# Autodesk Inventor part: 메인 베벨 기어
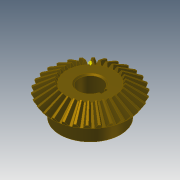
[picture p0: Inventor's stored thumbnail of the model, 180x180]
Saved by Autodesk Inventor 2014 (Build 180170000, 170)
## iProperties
Created: 2014-10
Part Number: 메인 베벨 기어
Material: Steel, Mild
Document SubType Name: Modeling
Designer: KYOUNG IL JANG
Categories: <?xml version="1.0" encoding="UTF-16"?> <MemberInstance><Categories><FamilyTemplate><FamilyTemplateParameter ValueType="xs:double" Id="1" ObjectReferenceKey="da
Mass: 269.583 g
Surface Area: 108.837 cm^2
Volume: 34.2981 cm^3
Density: 7.86 g/cm^3
Appearance: Brindle
CustomPartVersion: 1
Company: 한국ATC센터
Author: KYOUNG IL JANG
Revision Number: 1
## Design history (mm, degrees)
node "맨 위 점"
node "메쉬 평면2"
sketch "톱니 본체 스케치"
  geometry: L1 (0, 0)-(28.669, -21.997); L2 (28.669, -21.997)-(31.109, -18.336); L3 (31.109, -18.336)-(0, 0); L4 (30, -20)-(0, 0); L5 (17.219, -13.212)-(18.685, -11.013); L6 (28.669, -21.997)-(17.219, -13.212); L7 (31.109, -18.336)-(18.685, -11.013); L8 (0, -39.387)-(0, 6.564) reference; L9 (0, -20)-(31.109, -20)
  constraints: 16 end point, 4 point on line, 3 perpendicular, 2 collinear, 1 horizontal alignment, 1 vertical alignment
  dimensions: "d0" = 60 diameter of L4.start L8 (= da_de); "d1" = 57.33744 diameter of L1.end L8 (= da_dfe); "d2" = 62.2188 diameter of L2.end L8 (= da_dae); "d3" = 14.4 distance between parallel lines of L2 L5 (= da_b); "d4" = 18.3359 vertical distance of L2.end L1.start (= da_ve)
revolve "톱니 본체" sketch "톱니 본체 스케치" stored, may be unused: angle "d5" = 90 deg
node "시작점"
node "톱니 평면"
sketch "시작 스케치"
  geometry: L1 (0, -23.505)-(0, 10.645) reference; L2 (-0.709, -2.928)-(0.709, -2.928); A1 r 19.188 centre (-19.457, -7.014) between (-0.709, -2.928) and (-3.232, 3.229); A2 r 19.188 centre (19.457, -7.014) between (3.232, 3.229) and (0.709, -2.928); A3 r 57.403 centre (0, -54.083) between (3.232, 3.229) and (-3.232, 3.229); 1 further point
  constraints: 6 point on circle, 3 centre point, 3 symmetric about line, 2 end point, 1 coincident, 1 perpendicular, 1 other
  dimensions: "d7" = 19.18795 radius of A1 (= fd_rr); "d8" = 19.45712 horizontal distance of point (0, -54.083) A1.centre (= fd_x); "d9" = 47.06905 vertical distance of point (0, -54.083) A1.centre (= fd_y); "d57" = 57.40327 radius of A3 (= 0.5 x fd_dva + 0.3 x da_he); "d58" = 51.15527 distance from line of A3.centre L2 (= 0.5 x fd_dva - 1.12 x da_he)
node "끝점"
  node "끝 평면"
sketch "3D 스케치 오른쪽"
  node "Helical Curve Right" dims "d65" = 229.90621 (computed from da_dm, da_delta, da_beta), "d66" = 31.5, "d67" = 60 (= da_de), "d68" = -9.82794 (= -da_delta), "d69" = 8.10972 (computed from fd_loft, da_delta)
node "끝 평면 오른쪽"
sketch "끝 스케치 오른쪽"
  geometry: L1 (0, -41.54)-(0, 13.178) reference; L2 (-0.422, -1.69)-(0.422, -1.69); A1 r 11.427 centre (-11.587, -4.123) between (-0.422, -1.69) and (-1.925, 1.977); A2 r 11.427 centre (11.587, -4.123) between (1.925, 1.977) and (0.422, -1.69); A3 r 34.184 centre (0, -32.153) between (1.925, 1.977) and (-1.925, 1.977); 1 further point
  constraints: 6 point on circle, 3 centre point, 3 symmetric about line, 2 end point, 1 coincident, 1 perpendicular, 1 other
  dimensions: "d70" = 11.58699 horizontal distance of A3.centre A1.centre (computed from fd_x, fd_ratio); "d71" = 28.03028 vertical distance of point (0, -32.153) A1.centre (computed from fd_y, fd_ratio); "d72" = 11.4267 radius of A1 (computed from fd_rr, fd_ratio); "d73" = 30.46369 distance from line of point (0, -32.153) L2 (computed from d58, fd_ratio); "d74" = 34.18446 radius of A3 (computed from d57, fd_ratio)
feature "로프트 오른쪽" sketch "끝 스케치 오른쪽" dims "d75" = 0, "d77" = 0, "d79" = 0, "d80" = 90 deg, "d85" = 20, "d92" = 90 deg, "d93" = 90 deg, "da_teethtype" = 0 [user parameter]
sketch "3D 스케치 왼쪽"
  node "Helical Curve Left" dims "d26" = 229.90621 (computed from da_dm, da_delta, da_beta), "d27" = 8.10972 (computed from fd_loft, da_delta), "d28" = 60 (= da_de), "d29" = -9.82794 (= -da_delta)
node "끝 평면 왼쪽"
sketch "끝 스케치 왼쪽" dims "d56" = 10.3728 (derived)
  geometry: L1 (0, -43.753)-(0, 15.405) reference; L2 (-0.422, -1.678)-(0.422, -1.678); A1 r 11.427 centre (-11.587, -4.111) between (-0.422, -1.678) and (-1.925, 1.988); A2 r 11.427 centre (11.587, -4.111) between (1.925, 1.988) and (0.422, -1.678); A3 r 34.184 centre (0, -32.142) between (1.925, 1.988) and (-1.925, 1.988); 2 further points; 1 other entity
  constraints: 6 point on circle, 3 centre point, 3 symmetric about line, 2 end point, 1 coincident, 2 other
  dimensions: "d30" = 11.4267 radius of A1 (computed from fd_rr, fd_ratio); "d31" = 11.58699 horizontal distance of point (0, -32.142) A1.centre (computed from fd_x, fd_ratio); "d32" = 28.03028 vertical distance of A1.centre point (0, -32.142) (computed from fd_y, fd_ratio); "d61" = 34.18446 radius of A3 (computed from d57, fd_ratio); "d62" = 30.46369 distance from line of point (0, -32.142) L2 (computed from d58, fd_ratio)
feature "로프트 왼쪽" sketch "끝 스케치 왼쪽" dims "d35" = 0, "d37" = 0, "d39" = 0, "d40" = 90 deg, "d84" = 10, "d90" = 90 deg, "d91" = 90 deg, "da_teethtype" = 0 [user parameter]
sketch "본체 스케치"
  geometry: L1 (0, -35.038)-(0, -19.531) reference; L2 (28.669, -21.997)-(17.219, -13.212) reference; L3 (17.219, -13.212)-(0, -13.212); L4 (28.669, -21.997)-(0, -21.997)
  constraints: 4 end point, 2 perpendicular, 2 point on line
revolve "본체 고정" sketch "본체 스케치" stored, may be unused: angle "d46" = 90 deg
sketch "Sketch6"
  geometry: L1 (30, -20)-(0, 0) reference; L2 (0, -37.8)-(0, 6.3) reference
feature "피치 지름" sketch "Sketch6" dims angle "d47" = 90 deg
sketch "스케치8"
  geometry: C1 r 22.5 at (0, 0); 1 further point
  constraints: 1 centre point, 1 coincident
  dimensions: "d94" = 45 diameter of C1
extrude "돌출1" join sketch "스케치8" distance "d95" = 13; taper "d96" = 0 deg
sketch "스케치9"
  geometry: 1 further point
hole "구멍1" sketch "스케치9" diameter "d97" = 17; stored, may be unused: countersink angle "d101" = 90 deg, drill point angle "d103" = 118 deg; dims "d98" = 6, "d99" = 4, "d100" = 2, "d102" = 8
sketch "스케치10"
  geometry: L1 (8.124, 2.5)-(10.8, 2.5); L2 (10.8, 2.5)-(10.8, -2.5); L3 (10.8, -2.5)-(8.124, -2.5); A1 r 8.5 centre (0, 0) between (8.124, 2.5) and (8.124, -2.5) reference; 1 further point
  constraints: 6 end point, 2 parallel, 2 point on circle, 1 horizontal, 1 perpendicular
  dimensions: "d104" = 5 distance of L1.end L2.end; "d112" = 19.3 dimension on A1 L2
extrude "돌출2" cut sketch "스케치10" stored distance "d106" = 10; taper "d107" = 0 deg
chamfer "모따기1" distance "d108" = 1; stored, may be unused: second distance "d109" = 2, angle "d110" = 45 deg
fillet "모깎기1" dims "d111" = 2
body "Solid1"
feature "로프트" dims "d17" = 0, "d18" = 90 deg, "d19" = 0, "d20" = 90 deg, "d89" = 0, "da_teethtype" = 0 [user parameter]
pattern_circular "원형 패턴" dims angle "d22" = 360 deg, "d88" = 0, "da_teethtype" = 0 [user parameter]
pattern_circular "원형 패턴 오른쪽" dims angle "d82" = 360 deg, "da_teethtype" = 0 [user parameter]
pattern_circular "원형 패턴 왼쪽" dims angle "d42" = 360 deg, "da_teethtype" = 0 [user parameter]
sketch "끝 스케치"
  geometry: L1 (0, -15.359)-(0, 6.983) reference; L2 (-0.422, -1.69)-(0.422, -1.69); A1 r 11.427 centre (-11.587, -4.123) between (-0.422, -1.69) and (-1.925, 1.977); A2 r 11.427 centre (11.587, -4.123) between (1.925, 1.977) and (0.422, -1.69); A3 r 34.184 centre (0, -32.153) between (1.925, 1.977) and (-1.925, 1.977); 1 further point
  constraints: 6 point on circle, 3 centre point, 3 symmetric about line, 2 end point, 1 coincident, 1 other
  dimensions: "d12" = 11.4267 radius of A1 (computed from fd_rr, fd_ratio); "d15" = 11.58699 horizontal distance of A1.centre point (0, -32.153) (computed from fd_x, fd_ratio); "d16" = 28.03028 vertical distance of A1.centre point (0, -32.153) (computed from fd_y, fd_ratio); "d59" = 34.18446 radius of A3 (computed from d57, fd_ratio); "d60" = 30.46369 distance from line of A3.centre L2 (computed from d58, fd_ratio)
body "Srf1"
other parameters: "da_b" = 14.4 [user parameter; used in 2 equation terms], "da_de" = 60 [user parameter; used in 4 equation terms], "da_dae" = 62.2188 [user parameter; used in 2 equation terms], "da_dfe" = 57.33744 [user parameter; used in 1 equation term], "da_le" = 36.05551 [user parameter; used in 1 equation term], "da_omega" = 90 deg [user parameter; used in 1 equation term], "da_beta" = 0 [user parameter; used in 2 equation terms], "da_delta" = 9.82794 [user parameter; used in 8 equation terms], "da_alpha" = 20 deg [user parameter; used in 2 equation terms], "da_he" = 4.4 [user parameter; used in 4 equation terms], "da_ve" = 18.3359 [user parameter; used in 1 equation term], "fd_dv" = 108.16654 (computed from da_de, da_delta) [user parameter; used in 1 equation term], "fd_dva" = 112.16654 (computed from da_dae, da_delta) [user parameter; used in 3 equation terms], "fd_dvb" = 101.6433 (computed from fd_dv, da_alpha) [user parameter; used in 2 equation terms], "da_zv" = 540.83269 [user parameter; used in 1 equation term], "fd_loft" = 14.62 (= da_b + 0.05 x da_he) [user parameter; used in 4 equation terms], "fd_ratio" = 5.95514 (computed from da_le, fd_loft) [user parameter; used in 15 equation terms], "fd_rr" = 19.18795 (computed from fd_dd, fd_dvb) [user parameter; used in 6 equation terms], "fd_angle" = 0.29367 (computed from da_zv) [user parameter; used in 4 equation terms], "fd_x1" = 1.58802 (computed from da_dvw, fd_angle) [user parameter; used in 1 equation term], "fd_y1" = 54.05995 (computed from da_dvw, fd_angle) [user parameter; used in 1 equation term], "fd_x2" = 17.8691 (computed from fd_rr, fd_angle2, fd_angle) [user parameter; used in 1 equation term], "fd_y2" = 6.9909 (computed from fd_rr, fd_angle2, fd_angle) [user parameter; used in 1 equation term], "fd_x" = 19.45712 (= fd_x1 + fd_x2) [user parameter; used in 4 equation terms], "fd_y" = 47.06905 (= fd_y1 - fd_y2) [user parameter; used in 4 equation terms], "fd_angle2" = 3.43555 (computed from fd_dvb, fd_dd, da_alpha) [user parameter; used in 2 equation terms], "fd_dd" = 108.64654 (= fd_dva - 0.8 x da_he) [user parameter; used in 2 equation terms], "da_dvw" = 108.16654 [user parameter; used in 2 equation terms], "d11" = 14.62 (= fd_loft), "da_dm" = 48.01848 [user parameter; used in 2 equation terms], "da_x" = 0 [user parameter], "da_m" = 2 [user parameter], "d48" = 0, "d49" = 0, "d50" = 90 deg (= da_omega), "d51" = 6 deg (computed from da_z), "d52" = 0, "d53" = 0, "d54" = 0
